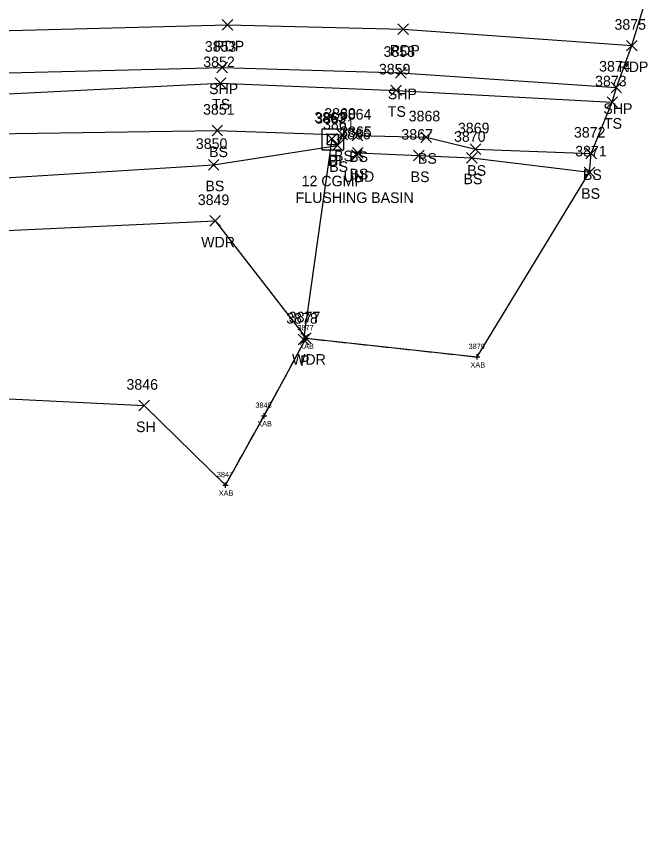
# Model space of a CAD drawing. Extents: x 1623612 to 1625808, y 621345 to 627748.
# Drawn here: x 1625667.6 to 1625788.4, y 627283.6 to 627436.5 of the extents above; entities that cross this region are included whole.
import ezdxf

# ---------------------------------------------------------------- set-up
doc = ezdxf.new("R2010")
doc.units = 0
for name, color, linetype in [('B_A', 7, 'Continuous'), ('B_I', 7, 'Continuous'), ('B_TIC', 7, 'Continuous'), ('BSUBM', 7, 'Continuous'), ('D_A', 7, 'Continuous'), ('D_C', 7, 'Continuous'), ('D_I', 7, 'Continuous'), ('D_TIC', 7, 'Continuous'), ('DCP', 7, 'Continuous'), ('DS', 7, 'Continuous'), ('L_A', 7, 'Continuous'), ('L_I', 7, 'Continuous'), ('L_TIC', 7, 'Continuous'), ('LAWA', 7, 'Continuous'), ('LELB', 7, 'Continuous'), ('LSOGP', 7, 'Continuous'), ('P_A', 7, 'Continuous'), ('P_I', 7, 'Continuous'), ('P_TIC', 7, 'Continuous'), ('PET', 7, 'Continuous'), ('PSP', 7, 'Continuous')]:
    doc.layers.add(name, color=color, linetype=linetype)

msp = doc.modelspace()

# ---------------------------------------------------------------- linework, layer by layer
at = {"layer": 'B_TIC'}
for p, q in [((1625722.37, 627375.67), (1625722.44, 627375.67)), ((1625754.7, 627372.14), (1625754.78, 627372.14)), ((1625714.44, 627361.04), (1625714.52, 627361.04)), ((1625707.16, 627347.94), (1625707.24, 627347.94))]:
    msp.add_line(p, q, dxfattribs=at)
for points in [[(1625721.86, 627375.67), (1625722.86, 627375.67)], [(1625722.36, 627375.17), (1625722.36, 627376.17)], [(1625754.2, 627372.14), (1625755.2, 627372.14)], [(1625754.7, 627371.64), (1625754.7, 627372.64)], [(1625714.44, 627360.54), (1625714.44, 627361.54)], [(1625713.94, 627361.04), (1625714.94, 627361.04)], [(1625706.66, 627347.94), (1625707.66, 627347.94)], [(1625707.16, 627347.44), (1625707.16, 627348.44)]]:
    msp.add_lwpolyline(points, dxfattribs=at)
at = {"layer": 'BSUBM'}
msp.add_lwpolyline([(1625707.16, 627347.94), (1625714.44, 627361.04), (1625722.36, 627375.67), (1625754.7, 627372.14)], dxfattribs=at)
at = {"layer": 'D_TIC'}
for points in [[(1625726.25, 627412.36), (1625728.25, 627414.36)], [(1625728.25, 627412.36), (1625726.25, 627414.36)], [(1625730.98, 627409.22), (1625732.98, 627411.22)], [(1625732.98, 627409.22), (1625730.98, 627411.22)], [(1625720.89, 627374.44), (1625722.89, 627376.44)], [(1625722.89, 627374.44), (1625720.89, 627376.44)]]:
    msp.add_lwpolyline(points, dxfattribs=at)
at = {"layer": 'DCP'}
msp.add_lwpolyline([(1625727.25, 627413.36), (1625721.89, 627375.44)], dxfattribs=at)
at = {"layer": 'DS'}
for p, q in [((1625725.41, 627415.19), (1625729.41, 627415.19)), ((1625725.41, 627411.19), (1625725.41, 627415.19)), ((1625729.41, 627415.19), (1625729.41, 627411.19)), ((1625726.41, 627412.19), (1625726.41, 627414.19)), ((1625726.41, 627414.19), (1625728.41, 627414.19)), ((1625727.42, 627413.19), (1625727.42, 627413.19)), ((1625727.42, 627413.19), (1625727.42, 627413.19)), ((1625728.41, 627414.19), (1625728.41, 627412.19)), ((1625728.41, 627412.19), (1625726.41, 627412.19)), ((1625729.41, 627411.19), (1625725.41, 627411.19))]:
    msp.add_line(p, q, dxfattribs=at)
at = {"layer": 'L_TIC'}
for points in [[(1625705.22, 627422.86), (1625707.22, 627424.86)], [(1625707.22, 627422.86), (1625705.22, 627424.86)], [(1625738.39, 627421.48), (1625740.39, 627423.48)], [(1625740.39, 627421.48), (1625738.39, 627423.48)], [(1625779.2, 627419.23), (1625781.2, 627421.23)], [(1625781.2, 627419.23), (1625779.2, 627421.23)], [(1625704.62, 627413.88), (1625706.62, 627415.88)], [(1625706.62, 627413.88), (1625704.62, 627415.88)], [(1625728.22, 627413.11), (1625730.22, 627415.11)], [(1625730.22, 627413.11), (1625728.22, 627415.11)], [(1625731.07, 627412.96), (1625733.07, 627414.96)], [(1625733.07, 627412.96), (1625731.07, 627414.96)], [(1625744.06, 627412.62), (1625746.06, 627414.62)], [(1625746.06, 627412.62), (1625744.06, 627414.62)], [(1625727.31, 627411.09), (1625729.31, 627413.09)], [(1625729.31, 627411.09), (1625727.31, 627413.09)], [(1625727.31, 627411.09), (1625729.31, 627413.09)], [(1625729.31, 627411.09), (1625727.31, 627413.09)], [(1625731.12, 627409.67), (1625733.12, 627411.67)], [(1625733.12, 627409.67), (1625731.12, 627411.67)], [(1625753.37, 627410.36), (1625755.37, 627412.36)], [(1625755.37, 627410.36), (1625753.37, 627412.36)], [(1625742.68, 627409.16), (1625744.68, 627411.16)], [(1625744.68, 627409.16), (1625742.68, 627411.16)], [(1625752.66, 627408.76), (1625754.66, 627410.76)], [(1625754.66, 627408.76), (1625752.66, 627410.76)], [(1625775.21, 627409.55), (1625777.21, 627411.55)], [(1625777.21, 627409.55), (1625775.21, 627411.55)], [(1625703.92, 627407.42), (1625705.92, 627409.42)], [(1625705.92, 627407.42), (1625703.92, 627409.42)], [(1625774.88, 627406), (1625776.88, 627408)], [(1625776.88, 627406), (1625774.88, 627408)], [(1625704.2, 627396.82), (1625706.2, 627398.82)], [(1625706.2, 627396.82), (1625704.2, 627398.82)], [(1625721.36, 627374.67), (1625723.36, 627376.67)], [(1625723.36, 627374.67), (1625721.36, 627376.67)], [(1625690.78, 627361.95), (1625692.78, 627363.95)], [(1625692.78, 627361.95), (1625690.78, 627363.95)]]:
    msp.add_lwpolyline(points, dxfattribs=at)
at = {"layer": 'LAWA'}
msp.add_lwpolyline([(1625369.47, 627290.4), (1625359.76, 627300.75), (1625391.49, 627312.5), (1625429.53, 627321.82), (1625462.89, 627344.16), (1625502.08, 627349.21), (1625537.95, 627356.18), (1625578.38, 627366.85), (1625606.23, 627394.72), (1625625.47, 627399.42), (1625663.03, 627395.89), (1625705.2, 627397.82), (1625722.36, 627375.67)], dxfattribs=at)
at = {"layer": 'LELB'}
for points in [[(1625111, 627101.13), (1625130.83, 627129.7), (1625156.28, 627161.64), (1625181.98, 627191.95), (1625204.33, 627215.18), (1625231.94, 627241.85), (1625257.57, 627263.61), (1625279.76, 627280.38), (1625303.46, 627296.59), (1625337.41, 627320.97), (1625377.29, 627343.7), (1625408.84, 627358.2), (1625449.74, 627375.28), (1625489.49, 627389.68), (1625533.09, 627402.6), (1625571.15, 627412.06), (1625624.18, 627419.27), (1625663.51, 627421.72), (1625706.22, 627423.86), (1625739.39, 627422.48), (1625780.2, 627420.23)], [(1625173.57, 627103.31), (1625198.3, 627138.01), (1625235.5, 627181.26), (1625257.15, 627208.81), (1625262.64, 627212.84), (1625293.35, 627251.67), (1625296.85, 627253.7), (1625299.51, 627255.19), (1625302.1, 627256.94), (1625301.55, 627257.93), (1625312.93, 627281.54), (1625341.78, 627310.69), (1625378.89, 627334.21), (1625411.91, 627351.77), (1625451.38, 627369.19), (1625491.07, 627383.46), (1625534.23, 627395.83), (1625572.47, 627404.98), (1625624.05, 627411.53), (1625663.08, 627414.27), (1625705.62, 627414.88), (1625729.22, 627414.11), (1625728.31, 627412.09)], [(1625732.07, 627413.96), (1625745.06, 627413.62), (1625754.37, 627411.36), (1625776.21, 627410.55)], [(1625300.5, 627239.13), (1625304.93, 627247.97), (1625302.85, 627256.04), (1625317.99, 627275.22), (1625334.99, 627300.87), (1625344.06, 627306.53), (1625379.52, 627332.99), (1625413.41, 627349.13), (1625452.73, 627364.82), (1625492.21, 627380.77), (1625534.81, 627392.22), (1625573.44, 627399.95), (1625624.56, 627404.74), (1625662.48, 627405.79), (1625704.92, 627408.42), (1625728.31, 627412.09)], [(1625732.12, 627410.67), (1625743.68, 627410.16), (1625753.66, 627409.76), (1625775.88, 627407)]]:
    msp.add_lwpolyline(points, dxfattribs=at)
at = {"layer": 'LSOGP'}
msp.add_lwpolyline([(1625653.44, 627364.88), (1625691.78, 627362.95), (1625707.16, 627347.94), (1625707.62, 627348.76), (1625708.07, 627349.58), (1625708.53, 627350.4), (1625708.98, 627351.21), (1625709.44, 627352.03), (1625709.89, 627352.85), (1625710.35, 627353.67), (1625710.8, 627354.49), (1625711.25, 627355.31), (1625711.71, 627356.13), (1625712.16, 627356.95), (1625712.62, 627357.76), (1625713.07, 627358.58), (1625713.53, 627359.4), (1625713.98, 627360.22), (1625714.44, 627361.04), (1625714.93, 627361.95), (1625715.43, 627362.87), (1625715.92, 627363.78), (1625716.42, 627364.7), (1625716.91, 627365.61), (1625717.41, 627366.52), (1625717.91, 627367.44), (1625718.4, 627368.35), (1625718.9, 627369.27), (1625719.39, 627370.18), (1625719.89, 627371.09), (1625720.38, 627372.01), (1625720.88, 627372.92), (1625721.37, 627373.84), (1625721.87, 627374.75), (1625722.36, 627375.67), (1625723.37, 627375.56), (1625724.38, 627375.44), (1625725.39, 627375.33), (1625726.4, 627375.22), (1625727.41, 627375.11), (1625728.42, 627375), (1625729.44, 627374.89), (1625730.45, 627374.78), (1625731.46, 627374.67), (1625732.47, 627374.56), (1625733.48, 627374.45), (1625734.49, 627374.34), (1625735.5, 627374.23), (1625736.51, 627374.12), (1625737.52, 627374.01), (1625738.53, 627373.9), (1625739.54, 627373.79), (1625740.55, 627373.68), (1625741.56, 627373.57), (1625742.57, 627373.46), (1625743.58, 627373.35), (1625744.59, 627373.24), (1625745.6, 627373.13), (1625746.61, 627373.02), (1625747.62, 627372.91), (1625748.63, 627372.8), (1625749.65, 627372.69), (1625750.66, 627372.58), (1625751.67, 627372.47), (1625752.68, 627372.36), (1625753.69, 627372.25), (1625754.7, 627372.14), (1625775.88, 627407), (1625776.21, 627410.55), (1625780.2, 627420.23), (1625780.96, 627423.03), (1625783.87, 627430.92), (1625788.41, 627445.83)], dxfattribs=at)
at = {"layer": 'P_TIC'}
for points in [[(1625706.55, 627433.84), (1625708.55, 627435.84)], [(1625708.55, 627433.84), (1625706.55, 627435.84)], [(1625739.73, 627433.04), (1625741.73, 627435.04)], [(1625741.73, 627433.04), (1625739.73, 627435.04)], [(1625782.87, 627429.92), (1625784.87, 627431.92)], [(1625784.87, 627429.92), (1625782.87, 627431.92)], [(1625705.52, 627425.77), (1625707.52, 627427.77)], [(1625707.52, 627425.77), (1625705.52, 627427.77)], [(1625739.26, 627424.81), (1625741.26, 627426.81)], [(1625741.26, 627424.81), (1625739.26, 627426.81)], [(1625779.96, 627422.03), (1625781.96, 627424.03)], [(1625781.96, 627422.03), (1625779.96, 627424.03)]]:
    msp.add_lwpolyline(points, dxfattribs=at)
at = {"layer": 'PET'}
msp.add_lwpolyline([(1625085.4, 627094.25), (1625110.27, 627129.17), (1625131.75, 627158.75), (1625155.63, 627186.85), (1625182.85, 627215.54), (1625208.2, 627240.19), (1625221.56, 627252.36), (1625248.45, 627276.07), (1625271.93, 627291.03), (1625296.8, 627310.27), (1625331.39, 627331.71), (1625373.16, 627355.88), (1625402.91, 627369.89), (1625447, 627387.72), (1625485.15, 627401.55), (1625532.49, 627414.31), (1625569.15, 627422.13), (1625624.7, 627430.37), (1625663.96, 627433.7), (1625707.55, 627434.84), (1625740.73, 627434.04), (1625783.87, 627430.92)], dxfattribs=at)
at = {"layer": 'PSP'}
msp.add_lwpolyline([(1625108.38, 627102.81), (1625128.19, 627131.96), (1625153.78, 627164.79), (1625179.21, 627194.48), (1625201.56, 627217.89), (1625229.72, 627244.56), (1625255.64, 627267.13), (1625276.98, 627284.12), (1625300.33, 627301.71), (1625335.15, 627324.9), (1625375.44, 627347.8), (1625406.32, 627362.88), (1625448.69, 627381.31), (1625487.83, 627394.48), (1625532.78, 627406.83), (1625570.78, 627414.59), (1625624.36, 627422.79), (1625663.55, 627425.73), (1625706.52, 627426.77), (1625740.26, 627425.81), (1625780.96, 627423.03)], dxfattribs=at)

# ---------------------------------------------------------------- texts
at = {"layer": 'B_A'}
for p in [(1625721.08, 627373.67), (1625753.42, 627370.14), (1625713.16, 627359.04), (1625705.88, 627345.94)]:
    msp.add_text('XAB', height=1, dxfattribs=at).set_placement(p)
at = {"layer": 'B_I'}
for s, p in [('3877', (1625720.73, 627377.17)), ('3879', (1625753.06, 627373.64)), ('3848', (1625712.81, 627362.54)), ('3847', (1625705.53, 627349.44))]:
    msp.add_text(s, height=1, dxfattribs=at).set_placement(p)
at = {"layer": 'D_A'}
for s, p in [('DI', (1625726.47, 627408.19)), ('P', (1625726.63, 627408.36)), ('UND', (1625729.45, 627405.22)), ('P', (1625721.26, 627370.44))]:
    msp.add_text(s, height=2, dxfattribs=at).set_placement(p)
at = {"layer": 'D_C'}
for s, p in [('12 CGMP', (1625721.54, 627404.36)), ('FLUSHING BASIN', (1625720.4, 627401.22))]:
    msp.add_text(s, height=2, dxfattribs=at).set_placement(p)
at = {"layer": 'D_I'}
for s, p in [('3863', (1625723.94, 627416.36)), ('3862', (1625724.11, 627416.19)), ('3866', (1625728.62, 627413.22)), ('3878', (1625718.63, 627378.44))]:
    msp.add_text(s, height=2, dxfattribs=at).set_placement(p)
at = {"layer": 'L_A'}
for s, p in [('TS', (1625704.63, 627418.86)), ('TS', (1625737.8, 627417.48)), ('TS', (1625778.61, 627415.23)), ('BS', (1625704.06, 627409.88)), ('BS', (1625727.66, 627409.11)), ('BS', (1625730.51, 627408.96)), ('BS', (1625743.5, 627408.62)), ('BS', (1625726.75, 627407.09)), ('BS', (1625726.75, 627407.09)), ('BS', (1625730.56, 627405.67)), ('BS', (1625742.12, 627405.16)), ('BS', (1625752.81, 627406.36)), ('BS', (1625774.65, 627405.55)), ('BS', (1625703.36, 627403.42)), ('BS', (1625752.1, 627404.76)), ('BS', (1625774.32, 627402)), ('WDR', (1625702.56, 627392.82)), ('WDR', (1625719.72, 627370.67)), ('SH', (1625690.27, 627357.95))]:
    msp.add_text(s, height=2, dxfattribs=at).set_placement(p)
at = {"layer": 'L_I'}
for s, p in [('3852', (1625702.96, 627426.86)), ('3859', (1625736.13, 627425.48)), ('3873', (1625776.94, 627423.23)), ('3851', (1625702.92, 627417.88)), ('3860', (1625725.82, 627417.11)), ('3864', (1625728.76, 627416.96)), ('3868', (1625741.75, 627416.62)), ('3861', (1625725.57, 627415.09)), ('3861', (1625725.57, 627415.09)), ('3869', (1625751.05, 627414.36)), ('3865', (1625728.81, 627413.67)), ('3867', (1625740.37, 627413.16)), ('3870', (1625750.31, 627412.76)), ('3872', (1625772.95, 627413.55)), ('3850', (1625701.57, 627411.42)), ('3871', (1625773.19, 627410)), ('3849', (1625701.93, 627400.82)), ('3877', (1625719.1, 627378.67)), ('3846', (1625688.46, 627365.95))]:
    msp.add_text(s, height=2, dxfattribs=at).set_placement(p)
at = {"layer": 'P_A'}
for s, p in [('RDP', (1625705.04, 627429.84)), ('RDP', (1625738.22, 627429.04)), ('RDP', (1625781.36, 627425.92)), ('SHP', (1625704.06, 627421.77)), ('SHP', (1625737.8, 627420.81)), ('SHP', (1625778.5, 627418.03))]:
    msp.add_text(s, height=2, dxfattribs=at).set_placement(p)
at = {"layer": 'P_I'}
for s, p in [('3875', (1625780.61, 627433.92)), ('3853', (1625703.26, 627429.77)), ('3858', (1625737, 627428.81)), ('3874', (1625777.7, 627426.03))]:
    msp.add_text(s, height=2, dxfattribs=at).set_placement(p)

doc.saveas('drawing.dxf')
